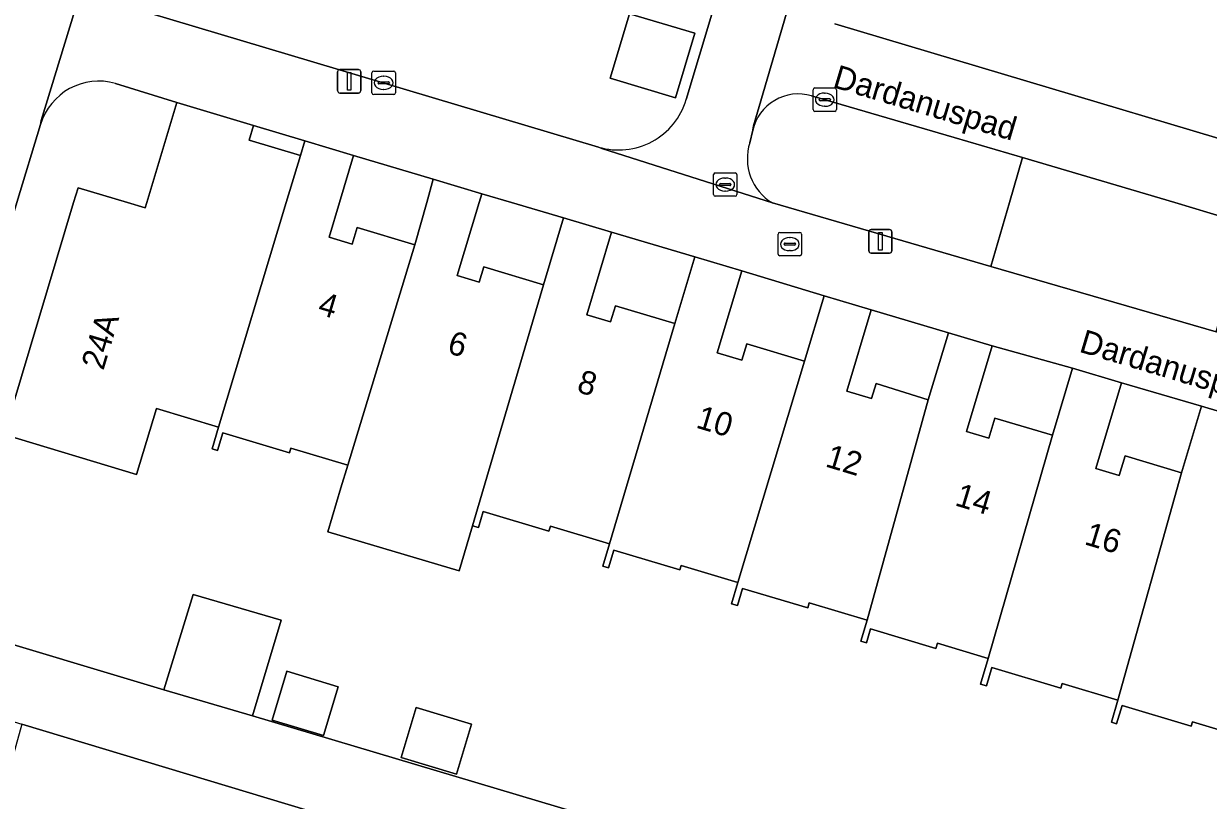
# Model space of a CAD drawing. Extents: x 162184 to 163154, y 385507 to 386516.
# Drawn here: x 162612.3 to 162662.8, y 386224.5 to 386257.6 of the extents above; entities that cross this region are included whole.
import ezdxf

# ---------------------------------------------------------------- set-up
doc = ezdxf.new("R2010")
doc.units = 0
for name, color, linetype in [('IMGEO_Brandkraan', 7, 'Continuous'), ('IMGEO_Erf', 7, 'Continuous'), ('IMGEO_Groenvoorziening', 7, 'Continuous'), ('IMGEO_Kolk', 7, 'Continuous'), ('IMGEO_Lichtmast', 7, 'Continuous'), ('IMGEO_Openbare_ruimte_label', 7, 'Continuous'), ('IMGEO_Pand', 7, 'Continuous'), ('IMGEO_Pand_nummerreeks', 7, 'Continuous'), ('IMGEO_Rioolput', 7, 'Continuous'), ('IMGEO_Voetpad_open', 7, 'Continuous')]:
    doc.layers.add(name, color=color, linetype=linetype)

msp = doc.modelspace()

# ---------------------------------------------------------------- linework, layer by layer
at = {"layer": 'IMGEO_Brandkraan'}
for p, q in [((162644.459, 386247.802), (162644.459, 386248.654)), ((162644.534, 386248.728), (162645.386, 386248.728)), ((162644.947, 386248.508), (162644.972, 386248.508)), ((162645.46, 386248.654), (162645.46, 386247.802)), ((162644.718, 386248.222), (162644.718, 386248.234)), ((162645.156, 386248.185), (162644.758, 386248.185)), ((162644.761, 386248.271), (162645.159, 386248.271)), ((162644.97, 386247.948), (162644.945, 386247.948)), ((162645.202, 386248.234), (162645.202, 386248.222)), ((162645.386, 386247.728), (162644.534, 386247.728))]:
    msp.add_line(p, q, dxfattribs=at)
for points in [[(162644.459, 386247.802), (162644.459, 386248.654)], [(162644.534, 386248.728), (162645.386, 386248.728)], [(162645.46, 386248.654), (162645.46, 386247.802)], [(162645.386, 386247.728), (162644.534, 386247.728)]]:
    msp.add_lwpolyline(points, dxfattribs=at)
for centre, radius, start, end in [((162644.536, 386248.652), 0.0765, 91.552, 178.448), ((162644.536, 386248.652), 0.0765, 91.552, 178.448), ((162645.384, 386248.652), 0.0765, 1.552, 88.448), ((162645.384, 386248.652), 0.0765, 1.552, 88.448), ((162644.758, 386248.231), 0.0403, 85.8775, 175.7526), ((162644.755, 386248.221), 0.0366, 178.938, 274.7102), ((162645.159, 386248.228), 0.043, 264.8664, 352.4533), ((162645.163, 386248.233), 0.0386, 1.7309, 96.639), ((162644.536, 386247.804), 0.0765, 181.552, 268.448), ((162644.536, 386247.804), 0.0765, 181.552, 268.448), ((162645.384, 386247.804), 0.0765, 271.552, 358.448), ((162645.384, 386247.804), 0.0765, 271.552, 358.448)]:
    msp.add_arc(centre, radius, start, end, dxfattribs=at)
for centre, major_axis, ratio, start_param, end_param in [((162644.946, 386248.228), (-0.387, 0.002), 0.722429, 4.712389, 7.853982), ((162644.971, 386248.228), (-0.39, 0.002), 0.717154, 1.570796, 4.712389)]:
    msp.add_ellipse(centre, major_axis=major_axis, ratio=ratio, start_param=start_param, end_param=end_param, dxfattribs=at)
at = {"layer": 'IMGEO_Erf'}
for points in [[(162640.538, 386254.388), (162642.771, 386261.827)], [(162617.569, 386258.112), (162636.798, 386252.368)], [(162646.882, 386257.628), (162672.402, 386250), (162716.792, 386236.732)], [(162648.254, 386232.187), (162645.785, 386232.927), (162645.72, 386232.711), (162642.939, 386233.544), (162642.721, 386232.815), (162642.466, 386232.891), (162642.737, 386233.798), (162640.328, 386234.52), (162640.271, 386234.329), (162637.451, 386235.174), (162637.225, 386234.421), (162636.977, 386234.496), (162637.26, 386235.442), (162634.749, 386236.194), (162634.686, 386235.982), (162631.877, 386236.823), (162631.673, 386236.143), (162631.423, 386236.218), (162630.848, 386234.288), (162625.257, 386235.963), (162625.813, 386237.832), (162626.103, 386238.801), (162623.675, 386239.529), (162623.614, 386239.327), (162620.768, 386240.18), (162620.543, 386239.429), (162620.314, 386239.498), (162620.592, 386240.427), (162617.942, 386241.221), (162617.099, 386238.407), (162611.442, 386240.102), (162614.408, 386250), (162614.598, 386250.633), (162616.71, 386250), (162617.464, 386249.774), (162617.532, 386250), (162618.811, 386254.268), (162616.2, 386255.078)], [(162612.998, 386253.328), (162611.995, 386250), (162607.649, 386235.575)], [(162609.673, 386231.789), (162618.261, 386229.221), (162619.516, 386233.282), (162623.27, 386232.189), (162622.043, 386228.107), (162647.252, 386220.589), (162647.783, 386222.491), (162651.141, 386221.554), (162650.593, 386219.592), (162667.509, 386214.547), (162668.325, 386217.27), (162670.595, 386216.59), (162669.78, 386213.87), (162672.525, 386213.051), (162678.17, 386211.368)], [(162664.505, 386227.144), (162662.128, 386227.855), (162662.07, 386227.664), (162659.127, 386228.545), (162658.894, 386227.773), (162658.684, 386227.839), (162658.951, 386228.771), (162656.576, 386229.482), (162656.519, 386229.292), (162653.579, 386230.172), (162653.343, 386229.386), (162653.093, 386229.461), (162653.42, 386230.552), (162651.252, 386231.202), (162651.187, 386230.986), (162648.406, 386231.819), (162648.226, 386231.216), (162647.985, 386231.288), (162648.254, 386232.187)]]:
    msp.add_lwpolyline(points, dxfattribs=at)
for points in [[(162640.905, 386257.22), (162640.081, 386254.469), (162637.293, 386255.304), (162638.116, 386258.055)], [(162622.088, 386253.286), (162621.9, 386252.659), (162624.085, 386252.004), (162624.271, 386252.627)], [(162626.355, 386252.002), (162625.755, 386250), (162625.311, 386248.521), (162626.285, 386248.229), (162626.498, 386248.941), (162628.961, 386248.203), (162629.47, 386250), (162629.75, 386250.991)], [(162633.093, 386250), (162631.819, 386250.371), (162631.708, 386250), (162630.774, 386246.883), (162631.707, 386246.604), (162631.904, 386247.262), (162634.454, 386246.497), (162635.31, 386249.354)], [(162637.353, 386248.742), (162636.295, 386245.215), (162637.313, 386244.91), (162637.519, 386245.595), (162640.049, 386244.837), (162640.902, 386247.684)], [(162642.908, 386247.083), (162641.862, 386243.592), (162642.912, 386243.277), (162643.119, 386243.968), (162645.58, 386243.23), (162646.419, 386246.027)], [(162648.429, 386245.424), (162647.389, 386241.955), (162648.446, 386241.638), (162648.641, 386242.288), (162650.864, 386241.582), (162651.722, 386244.45)], [(162653.592, 386243.891), (162652.499, 386240.24), (162653.453, 386239.954), (162653.709, 386240.807), (162656.16, 386240.073), (162657.02, 386242.943)], [(162659.111, 386242.317), (162658.014, 386238.653), (162659.006, 386238.356), (162659.257, 386239.196), (162661.66, 386238.477), (162662.51, 386241.316)], [(162625.067, 386227.269), (162622.873, 386227.928), (162623.5, 386230.012), (162625.693, 386229.353)], [(162630.743, 386225.628), (162628.383, 386226.338), (162629.023, 386228.466), (162631.383, 386227.757)]]:
    msp.add_lwpolyline(points, close=True, dxfattribs=at)
for centre, radius, start, end in [((162615.487, 386252.578), 2.6, 74.0837, 163.2324), ((162637.659, 386255.246), 3.004, 253.3427, 343.4049)]:
    msp.add_arc(centre, radius, start, end, dxfattribs=at)
at = {"layer": 'IMGEO_Groenvoorziening'}
for points in [[(162654.88, 386251.916), (162651.962, 386252.777), (162645.883, 386254.553)], [(162643.374, 386253.082), (162643.251, 386252.554)], [(162644.214, 386249.984), (162653.527, 386247.276), (162654.322, 386250), (162654.88, 386251.916)]]:
    msp.add_lwpolyline(points, dxfattribs=at)
for points in [[(162664.387, 386249.089), (162661.377, 386250), (162654.88, 386251.916), (162654.322, 386250), (162653.527, 386247.276), (162663.143, 386244.48)], [(162623.924, 386219.178), (162625.355, 386223.79), (162612.203, 386227.76), (162610.908, 386223.133)]]:
    msp.add_lwpolyline(points, close=True, dxfattribs=at)
for centre, radius, start, end in [((162645.325, 386252.629), 2.003, 73.8356, 166.9297), ((162645.364, 386251.88), 2.218, 162.3157, 238.7671)]:
    msp.add_arc(centre, radius, start, end, dxfattribs=at)
at = {"layer": 'IMGEO_Kolk'}
for p, q in [((162627.135, 386254.678), (162627.135, 386255.53)), ((162627.21, 386255.604), (162628.062, 386255.604)), ((162628.136, 386255.53), (162628.136, 386254.678)), ((162627.394, 386255.098), (162627.394, 386255.11)), ((162627.832, 386255.061), (162627.434, 386255.061)), ((162627.437, 386255.147), (162627.835, 386255.147)), ((162627.623, 386255.384), (162627.648, 386255.384)), ((162627.878, 386255.11), (162627.878, 386255.098)), ((162628.062, 386254.604), (162627.21, 386254.604)), ((162627.646, 386254.824), (162627.621, 386254.824)), ((162645.947, 386253.962), (162645.947, 386254.814)), ((162646.022, 386254.888), (162646.874, 386254.888)), ((162646.435, 386254.668), (162646.46, 386254.668)), ((162646.948, 386254.814), (162646.948, 386253.962)), ((162646.206, 386254.382), (162646.206, 386254.394)), ((162646.644, 386254.345), (162646.246, 386254.345)), ((162646.249, 386254.431), (162646.647, 386254.431)), ((162646.458, 386254.108), (162646.433, 386254.108)), ((162646.69, 386254.394), (162646.69, 386254.382)), ((162646.874, 386253.888), (162646.022, 386253.888))]:
    msp.add_line(p, q, dxfattribs=at)
for points in [[(162627.135, 386254.678), (162627.135, 386255.53)], [(162627.21, 386255.604), (162628.062, 386255.604)], [(162628.136, 386255.53), (162628.136, 386254.678)], [(162628.062, 386254.604), (162627.21, 386254.604)], [(162645.947, 386253.962), (162645.947, 386254.814)], [(162646.022, 386254.888), (162646.874, 386254.888)], [(162646.948, 386254.814), (162646.948, 386253.962)], [(162646.874, 386253.888), (162646.022, 386253.888)]]:
    msp.add_lwpolyline(points, dxfattribs=at)
for centre, radius, start, end in [((162627.212, 386255.528), 0.0765, 91.552, 178.448), ((162627.212, 386255.528), 0.0765, 91.552, 178.448), ((162628.06, 386255.528), 0.0765, 1.552, 88.448), ((162628.06, 386255.528), 0.0765, 1.552, 88.448), ((162627.434, 386255.107), 0.0403, 85.8775, 175.7526), ((162627.431, 386255.097), 0.0366, 178.938, 274.7102), ((162627.835, 386255.104), 0.043, 264.8664, 352.4533), ((162627.839, 386255.109), 0.0386, 1.7309, 96.639), ((162627.212, 386254.68), 0.0765, 181.552, 268.448), ((162627.212, 386254.68), 0.0765, 181.552, 268.448), ((162628.06, 386254.68), 0.0765, 271.552, 358.448), ((162628.06, 386254.68), 0.0765, 271.552, 358.448), ((162646.024, 386254.812), 0.0765, 91.552, 178.448), ((162646.024, 386254.812), 0.0765, 91.552, 178.448), ((162646.872, 386254.812), 0.0765, 1.552, 88.448), ((162646.872, 386254.812), 0.0765, 1.552, 88.448), ((162646.246, 386254.391), 0.0403, 85.8775, 175.7526), ((162646.243, 386254.381), 0.0366, 178.938, 274.7102), ((162646.647, 386254.388), 0.043, 264.8664, 352.4533), ((162646.651, 386254.393), 0.0386, 1.7309, 96.639), ((162646.024, 386253.964), 0.0765, 181.552, 268.448), ((162646.024, 386253.964), 0.0765, 181.552, 268.448), ((162646.872, 386253.964), 0.0765, 271.552, 358.448), ((162646.872, 386253.964), 0.0765, 271.552, 358.448)]:
    msp.add_arc(centre, radius, start, end, dxfattribs=at)
for centre, major_axis, ratio, start_param, end_param in [((162627.622, 386255.104), (-0.387, 0.002), 0.722429, 4.712389, 7.853982), ((162627.647, 386255.104), (-0.39, 0.002), 0.717154, 1.570796, 4.712389), ((162646.434, 386254.388), (-0.387, 0.002), 0.722429, 4.712389, 7.853982), ((162646.459, 386254.388), (-0.39, 0.002), 0.717154, 1.570796, 4.712389)]:
    msp.add_ellipse(centre, major_axis=major_axis, ratio=ratio, start_param=start_param, end_param=end_param, dxfattribs=at)
at = {"layer": 'IMGEO_Lichtmast'}
for p, q in [((162625.666, 386254.772), (162625.666, 386255.572)), ((162625.666, 386255.572), (162625.666, 386254.772)), ((162625.766, 386255.672), (162626.556, 386255.672)), ((162626.556, 386255.672), (162625.766, 386255.672)), ((162626.656, 386255.572), (162626.656, 386254.772)), ((162626.656, 386254.772), (162626.656, 386255.572)), ((162626.556, 386254.672), (162625.766, 386254.672)), ((162625.766, 386254.672), (162626.556, 386254.672)), ((162648.323, 386247.946), (162648.323, 386248.746)), ((162648.323, 386248.746), (162648.323, 386247.946)), ((162648.423, 386248.846), (162649.213, 386248.846)), ((162649.213, 386248.846), (162648.423, 386248.846)), ((162649.313, 386248.746), (162649.313, 386247.946)), ((162649.313, 386247.946), (162649.313, 386248.746)), ((162649.213, 386247.846), (162648.423, 386247.846)), ((162648.423, 386247.846), (162649.213, 386247.846))]:
    msp.add_line(p, q, dxfattribs=at)
for points in [[(162626.086, 386255.547), (162626.236, 386255.547), (162626.236, 386254.797), (162626.086, 386254.797), (162626.086, 386255.547)], [(162648.743, 386248.721), (162648.893, 386248.721), (162648.893, 386247.971), (162648.743, 386247.971), (162648.743, 386248.721)]]:
    msp.add_lwpolyline(points, dxfattribs=at)
for centre, start, end in [((162625.766, 386255.572), 90, 180), ((162625.766, 386255.572), 90, 180), ((162626.556, 386255.572), 0, 90), ((162626.556, 386255.572), 360, 90), ((162625.766, 386254.772), 180, 270), ((162625.766, 386254.772), 180, 270), ((162626.556, 386254.772), 270, 0), ((162626.556, 386254.772), 270, 0), ((162648.423, 386248.746), 90, 180), ((162648.423, 386248.746), 90, 180), ((162649.213, 386248.746), 0, 90), ((162649.213, 386248.746), 360, 90), ((162648.423, 386247.946), 180, 270), ((162648.423, 386247.946), 180, 270), ((162649.213, 386247.946), 270, 0), ((162649.213, 386247.946), 270, 0)]:
    msp.add_arc(centre, 0.1, start, end, dxfattribs=at)
at = {"layer": 'IMGEO_Pand'}
for points in [[(162640.081, 386254.469), (162640.905, 386257.22), (162638.116, 386258.055), (162637.293, 386255.304)], [(162618.811, 386254.268), (162617.532, 386250), (162617.464, 386249.774), (162616.71, 386250), (162614.598, 386250.633), (162614.408, 386250), (162611.442, 386240.102), (162617.099, 386238.407), (162617.942, 386241.221), (162620.592, 386240.427), (162623.48, 386250), (162624.085, 386252.004), (162621.9, 386252.659), (162622.088, 386253.286)], [(162624.271, 386252.627), (162624.085, 386252.004), (162623.48, 386250), (162620.592, 386240.427), (162620.314, 386239.498), (162620.543, 386239.429), (162620.768, 386240.18), (162623.614, 386239.327), (162623.675, 386239.529), (162626.103, 386238.801), (162628.961, 386248.203), (162626.498, 386248.941), (162626.285, 386248.229), (162625.311, 386248.521), (162625.755, 386250), (162626.355, 386252.002)], [(162629.75, 386250.991), (162629.47, 386250), (162628.961, 386248.203), (162626.103, 386238.801), (162625.813, 386237.832), (162625.257, 386235.963), (162630.848, 386234.288), (162631.423, 386236.218), (162634.454, 386246.497), (162631.904, 386247.262), (162631.707, 386246.604), (162630.774, 386246.883), (162631.708, 386250), (162631.819, 386250.371)], [(162635.31, 386249.354), (162634.454, 386246.497), (162631.423, 386236.218), (162631.673, 386236.143), (162631.877, 386236.823), (162634.686, 386235.982), (162634.749, 386236.194), (162637.26, 386235.442), (162640.049, 386244.837), (162637.519, 386245.595), (162637.313, 386244.91), (162636.295, 386245.215), (162637.353, 386248.742)], [(162640.902, 386247.684), (162640.049, 386244.837), (162637.26, 386235.442), (162636.977, 386234.496), (162637.225, 386234.421), (162637.451, 386235.174), (162640.271, 386234.329), (162640.328, 386234.52), (162642.737, 386233.798), (162645.58, 386243.23), (162643.119, 386243.968), (162642.912, 386243.277), (162641.862, 386243.592), (162642.908, 386247.083)], [(162646.419, 386246.027), (162645.58, 386243.23), (162642.737, 386233.798), (162642.466, 386232.891), (162642.721, 386232.815), (162642.939, 386233.544), (162645.72, 386232.711), (162645.785, 386232.927), (162648.254, 386232.187), (162650.864, 386241.582), (162648.641, 386242.288), (162648.446, 386241.638), (162647.389, 386241.955), (162648.429, 386245.424)], [(162651.722, 386244.45), (162650.864, 386241.582), (162648.254, 386232.187), (162647.985, 386231.288), (162648.226, 386231.216), (162648.406, 386231.819), (162651.187, 386230.986), (162651.252, 386231.202), (162653.42, 386230.552), (162656.16, 386240.073), (162653.709, 386240.807), (162653.453, 386239.954), (162652.499, 386240.24), (162653.592, 386243.891)], [(162657.02, 386242.943), (162656.16, 386240.073), (162653.42, 386230.552), (162653.093, 386229.461), (162653.343, 386229.386), (162653.579, 386230.172), (162656.519, 386229.292), (162656.576, 386229.482), (162658.951, 386228.771), (162661.66, 386238.477), (162659.257, 386239.196), (162659.006, 386238.356), (162658.014, 386238.653), (162659.111, 386242.317)], [(162662.51, 386241.316), (162661.66, 386238.477), (162658.951, 386228.771), (162658.684, 386227.839), (162658.894, 386227.773), (162659.127, 386228.545), (162662.07, 386227.664), (162662.128, 386227.855), (162664.505, 386227.144), (162667.255, 386236.804), (162664.805, 386237.537), (162664.551, 386236.688), (162663.555, 386236.986), (162664.659, 386240.673)], [(162623.27, 386232.189), (162619.516, 386233.282), (162618.261, 386229.221), (162622.043, 386228.107)], [(162625.067, 386227.269), (162625.693, 386229.353), (162623.5, 386230.012), (162622.873, 386227.928)], [(162630.743, 386225.628), (162631.383, 386227.757), (162629.023, 386228.466), (162628.383, 386226.338)]]:
    msp.add_lwpolyline(points, close=True, dxfattribs=at)
at = {"layer": 'IMGEO_Rioolput'}
for p, q in [((162641.703, 386250.34), (162641.703, 386251.192)), ((162641.778, 386251.266), (162642.63, 386251.266)), ((162642.191, 386251.046), (162642.216, 386251.046)), ((162642.704, 386251.192), (162642.704, 386250.34)), ((162641.962, 386250.76), (162641.962, 386250.772)), ((162642.4, 386250.723), (162642.002, 386250.723)), ((162642.005, 386250.809), (162642.403, 386250.809)), ((162642.214, 386250.486), (162642.189, 386250.486)), ((162642.446, 386250.772), (162642.446, 386250.76)), ((162642.63, 386250.266), (162641.778, 386250.266))]:
    msp.add_line(p, q, dxfattribs=at)
for points in [[(162641.703, 386250.34), (162641.703, 386251.192)], [(162641.778, 386251.266), (162642.63, 386251.266)], [(162642.704, 386251.192), (162642.704, 386250.34)], [(162642.63, 386250.266), (162641.778, 386250.266)]]:
    msp.add_lwpolyline(points, dxfattribs=at)
for centre, radius, start, end in [((162641.78, 386251.19), 0.0765, 91.552, 178.448), ((162641.78, 386251.19), 0.0765, 91.552, 178.448), ((162642.628, 386251.19), 0.0765, 1.552, 88.448), ((162642.628, 386251.19), 0.0765, 1.552, 88.448), ((162642.002, 386250.769), 0.0403, 85.8775, 175.7526), ((162641.999, 386250.759), 0.0366, 178.938, 274.7102), ((162642.403, 386250.766), 0.043, 264.8664, 352.4533), ((162642.407, 386250.771), 0.0386, 1.7309, 96.639), ((162641.78, 386250.342), 0.0765, 181.552, 268.448), ((162641.78, 386250.342), 0.0765, 181.552, 268.448), ((162642.628, 386250.342), 0.0765, 271.552, 358.448), ((162642.628, 386250.342), 0.0765, 271.552, 358.448)]:
    msp.add_arc(centre, radius, start, end, dxfattribs=at)
for centre, major_axis, ratio, start_param, end_param in [((162642.19, 386250.766), (-0.387, 0.002), 0.722429, 4.712389, 7.853982), ((162642.215, 386250.766), (-0.39, 0.002), 0.717154, 1.570796, 4.712389)]:
    msp.add_ellipse(centre, major_axis=major_axis, ratio=ratio, start_param=start_param, end_param=end_param, dxfattribs=at)
at = {"layer": 'IMGEO_Voetpad_open'}
for points in [[(162607.649, 386235.575), (162611.995, 386250), (162612.998, 386253.328), (162613.032, 386253.495), (162615.469, 386261.509), (162615.574, 386261.809), (162634.243, 386324.299)], [(162657.293, 386310.356), (162656.644, 386308.039), (162656.021, 386305.958), (162654.99, 386302.571), (162654.37, 386300.5), (162653.3, 386297.043), (162652.687, 386294.996), (162651.669, 386291.532), (162651.047, 386289.457), (162650.039, 386286.051), (162649.408, 386283.944), (162648.381, 386280.445), (162647.769, 386278.403), (162646.722, 386274.973), (162646.1, 386272.895), (162645.017, 386269.369), (162644.396, 386267.294), (162643.389, 386263.891), (162642.771, 386261.827), (162640.538, 386254.388)], [(162643.251, 386252.554), (162643.374, 386253.082), (162643.405, 386253.266), (162645.405, 386260.084), (162645.471, 386260.26), (162650.909, 386278.146), (162650.918, 386278.187), (162653.011, 386285.784)], [(162615.574, 386261.809), (162615.469, 386261.509), (162613.032, 386253.495), (162612.998, 386253.328)], [(162645.471, 386260.26), (162645.405, 386260.084), (162643.405, 386253.266), (162643.374, 386253.082)], [(162687.062, 386237.292), (162681.784, 386238.878), (162666.113, 386243.587), (162663.143, 386244.48), (162653.527, 386247.276), (162644.214, 386249.984), (162636.944, 386252.303), (162636.798, 386252.368), (162617.569, 386258.112)], [(162716.792, 386236.732), (162672.402, 386250), (162646.882, 386257.628)], [(162616.2, 386255.078), (162618.811, 386254.268), (162622.088, 386253.286), (162624.271, 386252.627), (162626.355, 386252.002), (162629.75, 386250.991), (162631.819, 386250.371), (162633.093, 386250), (162635.31, 386249.354), (162637.353, 386248.742), (162640.902, 386247.684), (162642.908, 386247.083), (162646.419, 386246.027), (162648.429, 386245.424), (162651.722, 386244.45), (162653.592, 386243.891), (162657.02, 386242.943), (162659.111, 386242.317), (162662.51, 386241.316), (162664.659, 386240.673)], [(162645.883, 386254.553), (162651.962, 386252.777), (162654.88, 386251.916), (162661.377, 386250), (162664.387, 386249.089), (162667.423, 386248.17), (162683.122, 386243.418), (162688.44, 386241.808), (162688.724, 386241.748), (162694.855, 386239.955), (162694.999, 386239.897), (162698.728, 386238.77), (162705.018, 386236.868), (162713.048, 386234.47), (162716.435, 386233.458)], [(162636.798, 386252.368), (162636.944, 386252.303), (162644.214, 386249.984)], [(162682.213, 386203.881), (162682.581, 386204.898), (162678.17, 386211.368), (162672.525, 386213.051), (162669.78, 386213.87), (162669.757, 386213.792), (162667.487, 386214.472), (162667.509, 386214.547), (162650.593, 386219.592), (162650.585, 386219.562), (162647.227, 386220.499), (162647.252, 386220.589), (162622.043, 386228.107), (162618.261, 386229.221), (162609.673, 386231.789), (162606.797, 386232.654), (162605.402, 386227.874)], [(162607.767, 386229.099), (162612.203, 386227.76), (162625.355, 386223.79), (162629.025, 386222.685)]]:
    msp.add_lwpolyline(points, dxfattribs=at)
for centre, radius, start, end in [((162615.487, 386252.578), 2.6, 74.0837, 163.2324), ((162645.325, 386252.629), 2.003, 73.8356, 166.9297), ((162637.659, 386255.246), 3.004, 253.3427, 343.4049), ((162645.364, 386251.88), 2.218, 162.3157, 238.7671)]:
    msp.add_arc(centre, radius, start, end, dxfattribs=at)

# ---------------------------------------------------------------- texts
at = {"layer": 'IMGEO_Openbare_ruimte_label'}
for p in [(162646.746, 386254.929), (162657.256, 386243.646)]:
    msp.add_text('Dardanuspad', height=1, rotation=343.3776, dxfattribs=at).set_placement(p)
at = {"layer": 'IMGEO_Pand_nummerreeks'}
for s, rotation, p in [('4', 343.2856, (162624.778, 386245.256)), ('24A', 73.3188, (162615.678, 386242.811)), ('6', 343.2856, (162630.301, 386243.598)), ('8', 343.2856, (162635.829, 386241.938)), ('10', 343.2856, (162640.912, 386240.411)), ('12', 343.2856, (162646.43, 386238.754)), ('14', 343.2856, (162651.956, 386237.095)), ('16', 343.2856, (162657.48, 386235.436))]:
    msp.add_text(s, height=1, rotation=rotation, dxfattribs=at).set_placement(p)

doc.saveas('drawing.dxf')
